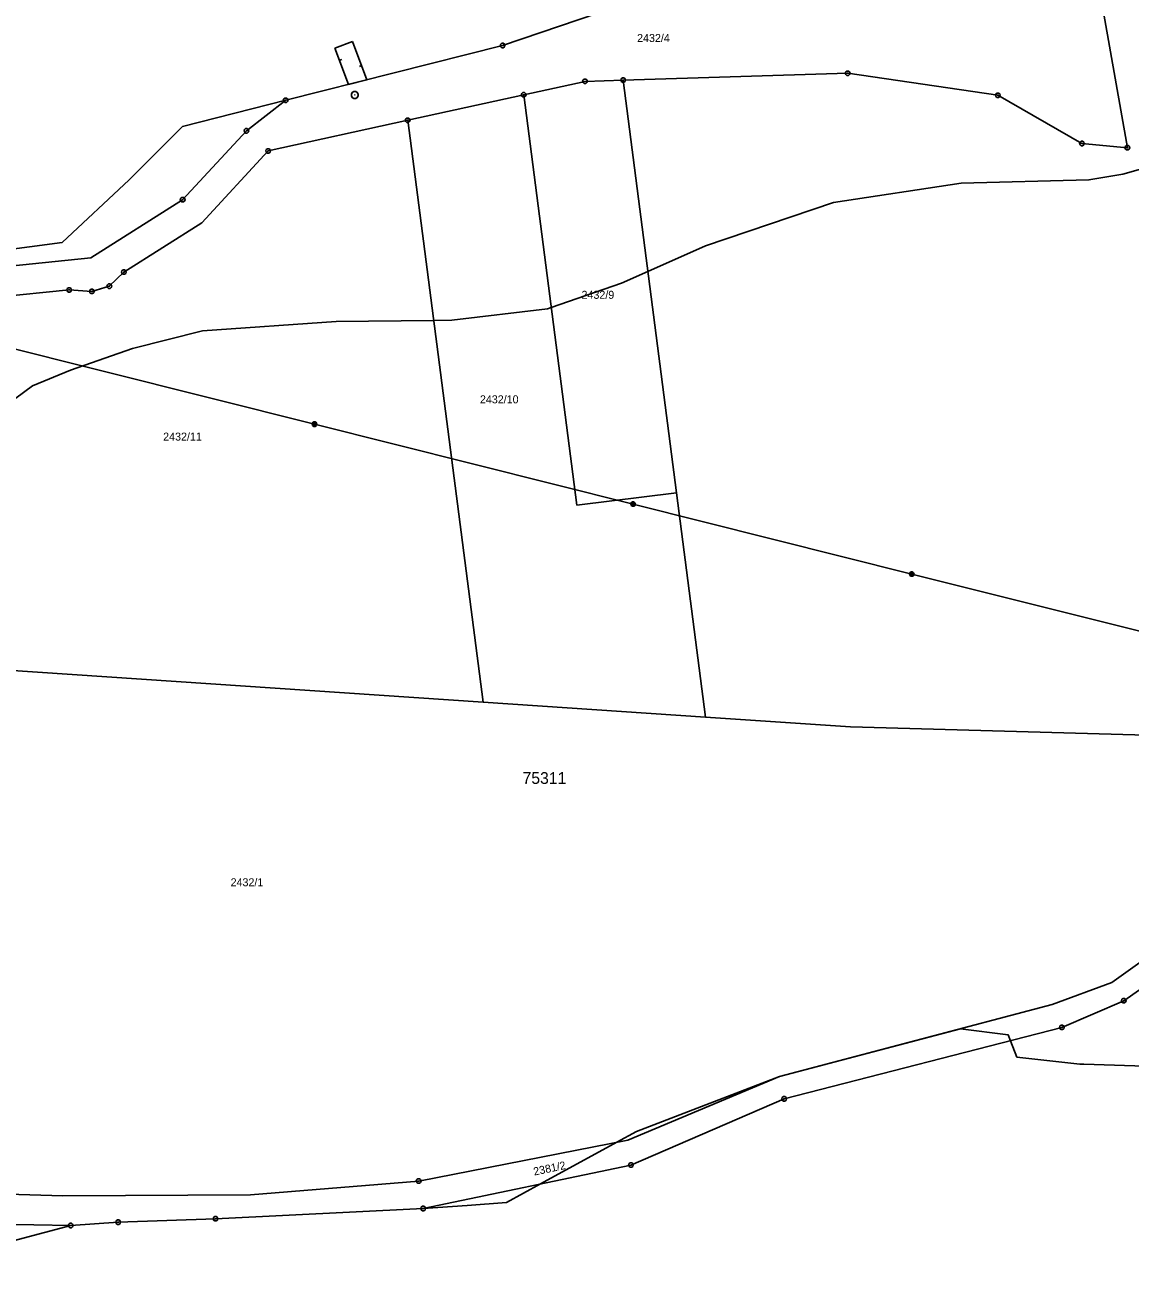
# Model space of a CAD drawing. Extents: x -760611 to -758411, y -1176479 to -1174807.
# Drawn here: x -758977.4 to -758742.6, y -1175366.9 to -1175101.5 of the extents above; entities that cross this region are included whole.
import ezdxf

# ---------------------------------------------------------------- set-up
doc = ezdxf.new("R2010")
doc.units = 0
for name, color, linetype in [('1', 7, 'Continuous'), ('11', 7, 'Continuous'), ('13', 7, 'Continuous'), ('2', 7, 'Continuous'), ('6', 7, 'Continuous'), ('8', 7, 'Continuous')]:
    doc.layers.add(name, color=color, linetype=linetype)

msp = doc.modelspace()

# ---------------------------------------------------------------- linework, layer by layer
at = {"layer": '1'}
for p, q in [((-758855.66, -1175098.98), (-758875.91, -1175105.89)), ((-758748.15, -1175099.24), (-758743.15, -1175127.6)), ((-758875.91, -1175105.89), (-758922, -1175117.53)), ((-758858.39, -1175113.5), (-758871.42, -1175116.36)), ((-758850.29, -1175113.25), (-758858.39, -1175113.5)), ((-758802.58, -1175111.79), (-758850.29, -1175113.25)), ((-758838.93, -1175200.97), (-758850.29, -1175113.25)), ((-758770.67, -1175116.46), (-758802.58, -1175111.79)), ((-758943.96, -1175123.07), (-758922, -1175117.53)), ((-758930.35, -1175124.02), (-758922, -1175117.53)), ((-758871.42, -1175116.36), (-758896.08, -1175121.78)), ((-758871.42, -1175116.36), (-758860.12, -1175203.57)), ((-758752.8, -1175126.72), (-758770.67, -1175116.46)), ((-758943.96, -1175123.07), (-758955.25, -1175134.45)), ((-758943.9, -1175138.65), (-758930.35, -1175124.02)), ((-758896.08, -1175121.78), (-758925.73, -1175128.3)), ((-758896.08, -1175121.78), (-758880.06, -1175245.42)), ((-758743.15, -1175127.6), (-758752.8, -1175126.72)), ((-758925.73, -1175128.3), (-758939.85, -1175143.55)), ((-758955.25, -1175134.45), (-758969.53, -1175147.78)), ((-758963.42, -1175151.02), (-758943.9, -1175138.65)), ((-758939.85, -1175143.55), (-758956.4, -1175154.03)), ((-758969.53, -1175147.78), (-758992.89, -1175150.76)), ((-758994.13, -1175154.13), (-758963.42, -1175151.02)), ((-758956.4, -1175154.03), (-758959.48, -1175157.03)), ((-758968.01, -1175157.83), (-758992.28, -1175160.27)), ((-758963.18, -1175158.15), (-758968.01, -1175157.83)), ((-758959.48, -1175157.03), (-758963.18, -1175158.15)), ((-758860.12, -1175203.57), (-758838.93, -1175200.97)), ((-758832.76, -1175248.61), (-758838.93, -1175200.97)), ((-758880.06, -1175245.42), (-758982.14, -1175238.54)), ((-758880.06, -1175245.42), (-758832.76, -1175248.61)), ((-758832.76, -1175248.61), (-758801.99, -1175250.69)), ((-758695.3, -1175253.59), (-758801.99, -1175250.69)), ((-758730.9, -1175293.88), (-758746.46, -1175305.02)), ((-758743.91, -1175308.85), (-758726.91, -1175296.89)), ((-758746.46, -1175305.02), (-758759.1, -1175309.68)), ((-758759.1, -1175309.68), (-758817.04, -1175324.96)), ((-758743.91, -1175308.85), (-758757.06, -1175314.54)), ((-758757.06, -1175314.54), (-758816.07, -1175329.71)), ((-758817.04, -1175324.96), (-758849.31, -1175338.47)), ((-758816.07, -1175329.71), (-758848.63, -1175343.77)), ((-758849.31, -1175338.47), (-758893.74, -1175347.18)), ((-758848.63, -1175343.77), (-758892.8, -1175353.02)), ((-758893.74, -1175347.18), (-758929.46, -1175350.12)), ((-758969.35, -1175350.34), (-758984.06, -1175349.84)), ((-758929.46, -1175350.12), (-758969.35, -1175350.34)), ((-758936.92, -1175355.2), (-758892.8, -1175353.02)), ((-758991.35, -1175356.15), (-758967.69, -1175356.63)), ((-758967.69, -1175356.63), (-758957.61, -1175355.92)), ((-758957.61, -1175355.92), (-758936.92, -1175355.2))]:
    msp.add_line(p, q, dxfattribs=at)
at = {"layer": '11'}
for points in [[(-758613.2, -1175122.93), (-758673.25, -1175117.07), (-758689.79, -1175118.68), (-758704.22, -1175121.99), (-758744.12, -1175133.22), (-758751.33, -1175134.45), (-758778.47, -1175135.16), (-758805.62, -1175139.26), (-758832.79, -1175148.43), (-758845.03, -1175153.89), (-758850.63, -1175156.38), (-758865.57, -1175161.54), (-758866.34, -1175161.81), (-758886.7, -1175164.24), (-758890.57, -1175164.29), (-758911.29, -1175164.54), (-758939.71, -1175166.52), (-758954.56, -1175170.25), (-758967.72, -1175174.84), (-758975.79, -1175178.19), (-758988.73, -1175187.68)], [(-758658.74, -1175325.4), (-758661.28, -1175325.32), (-758752.38, -1175322.35), (-758753.28, -1175322.32), (-758766.61, -1175320.84), (-758767.99, -1175317.35), (-758768.47, -1175316.14), (-758778.64, -1175314.83), (-758817.04, -1175324.96), (-758847.47, -1175336.66), (-758851.6, -1175338.92), (-758867.88, -1175347.8), (-758875.08, -1175351.73), (-758883.45, -1175352.34), (-758892.8, -1175353.02)], [(-758993.67, -1175366.93), (-758989.69, -1175362.44), (-758985.6, -1175361.36), (-758967.69, -1175356.63), (-758957.61, -1175355.92), (-758936.92, -1175355.2), (-758892.8, -1175353.02)]]:
    msp.add_lwpolyline(points, dxfattribs=at)
at = {"layer": '13'}
for p, q in [((-758911.53, -1175106.42), (-758907.79, -1175105.02)), ((-758907.79, -1175105.02), (-758904.74, -1175113.17)), ((-758908.65, -1175114.16), (-758911.53, -1175106.42)), ((-758910.57, -1175109.01), (-758910.1, -1175108.83)), ((-758905.86, -1175110.17), (-758906.33, -1175110.35)), ((-758904.74, -1175113.17), (-758908.65, -1175114.16))]:
    msp.add_line(p, q, dxfattribs=at)
at = {"layer": '6'}
for p, q in [((-758915.88, -1175186.35), (-758992.56, -1175167.12)), ((-758848.19, -1175203.34), (-758915.88, -1175186.35)), ((-758788.97, -1175218.21), (-758848.19, -1175203.34)), ((-758725.44, -1175234.14), (-758788.97, -1175218.21))]:
    msp.add_line(p, q, dxfattribs=at)
for points in [[(-758916.03, -1175185.87), (-758915.72, -1175185.87), (-758915.47, -1175186.05), (-758915.37, -1175186.34), (-758915.47, -1175186.63), (-758915.72, -1175186.81), (-758916.03, -1175186.81), (-758916.28, -1175186.63), (-758916.38, -1175186.34), (-758916.28, -1175186.05), (-758916.03, -1175185.87), (-758916, -1175185.91), (-758915.76, -1175185.91), (-758915.6, -1175185.99), (-758916.16, -1175185.99), (-758916.24, -1175186.07), (-758915.52, -1175186.07), (-758915.52, -1175186.15), (-758916.24, -1175186.15), (-758916.28, -1175186.23), (-758915.48, -1175186.23), (-758915.44, -1175186.31), (-758916.32, -1175186.31), (-758916.32, -1175186.39), (-758915.44, -1175186.39), (-758915.47, -1175186.47), (-758916.28, -1175186.47), (-758916.27, -1175186.55), (-758915.46, -1175186.55), (-758915.51, -1175186.63), (-758916.23, -1175186.63), (-758916.15, -1175186.71), (-758915.59, -1175186.71), (-758915.7, -1175186.79), (-758916.04, -1175186.79)], [(-758848.34, -1175202.86), (-758848.03, -1175202.86), (-758847.78, -1175203.04), (-758847.68, -1175203.33), (-758847.78, -1175203.62), (-758848.03, -1175203.8), (-758848.34, -1175203.8), (-758848.59, -1175203.62), (-758848.69, -1175203.33), (-758848.59, -1175203.04), (-758848.34, -1175202.86), (-758848.31, -1175202.9), (-758848.07, -1175202.9), (-758847.91, -1175202.98), (-758848.47, -1175202.98), (-758848.55, -1175203.06), (-758847.83, -1175203.06), (-758847.83, -1175203.14), (-758848.55, -1175203.14), (-758848.59, -1175203.22), (-758847.79, -1175203.22), (-758847.75, -1175203.3), (-758848.63, -1175203.3), (-758848.63, -1175203.38), (-758847.75, -1175203.38), (-758847.78, -1175203.46), (-758848.59, -1175203.46), (-758848.58, -1175203.54), (-758847.77, -1175203.54), (-758847.82, -1175203.62), (-758848.54, -1175203.62), (-758848.46, -1175203.7), (-758847.9, -1175203.7), (-758848.01, -1175203.78), (-758848.35, -1175203.78)], [(-758789.12, -1175217.73), (-758788.81, -1175217.73), (-758788.56, -1175217.91), (-758788.46, -1175218.2), (-758788.56, -1175218.49), (-758788.81, -1175218.67), (-758789.12, -1175218.67), (-758789.37, -1175218.49), (-758789.47, -1175218.2), (-758789.37, -1175217.91), (-758789.12, -1175217.73), (-758789.09, -1175217.77), (-758788.85, -1175217.77), (-758788.69, -1175217.85), (-758789.25, -1175217.85), (-758789.33, -1175217.93), (-758788.61, -1175217.93), (-758788.61, -1175218.01), (-758789.33, -1175218.01), (-758789.37, -1175218.09), (-758788.57, -1175218.09), (-758788.53, -1175218.17), (-758789.41, -1175218.17), (-758789.41, -1175218.25), (-758788.53, -1175218.25), (-758788.56, -1175218.33), (-758789.37, -1175218.33), (-758789.36, -1175218.41), (-758788.55, -1175218.41), (-758788.6, -1175218.49), (-758789.32, -1175218.49), (-758789.24, -1175218.57), (-758788.68, -1175218.57), (-758788.79, -1175218.65), (-758789.13, -1175218.65)]]:
    msp.add_lwpolyline(points, dxfattribs=at)
at = {"layer": '8'}
for p, q in [((-758876.03, -1175105.89), (-758875.79, -1175105.89)), ((-758858.51, -1175113.5), (-758858.27, -1175113.5)), ((-758850.41, -1175113.25), (-758850.17, -1175113.25)), ((-758802.7, -1175111.79), (-758802.46, -1175111.79)), ((-758922.12, -1175117.53), (-758921.88, -1175117.53)), ((-758907.37, -1175116.4), (-758907.27, -1175116.4)), ((-758871.54, -1175116.36), (-758871.3, -1175116.36)), ((-758770.79, -1175116.46), (-758770.55, -1175116.46)), ((-758930.47, -1175124.02), (-758930.23, -1175124.02)), ((-758896.2, -1175121.78), (-758895.96, -1175121.78)), ((-758752.92, -1175126.72), (-758752.68, -1175126.72)), ((-758925.85, -1175128.3), (-758925.61, -1175128.3)), ((-758743.27, -1175127.6), (-758743.03, -1175127.6)), ((-758944.02, -1175138.65), (-758943.78, -1175138.65)), ((-758956.52, -1175154.03), (-758956.28, -1175154.03)), ((-758968.13, -1175157.83), (-758967.89, -1175157.83)), ((-758963.3, -1175158.15), (-758963.06, -1175158.15)), ((-758959.6, -1175157.03), (-758959.36, -1175157.03)), ((-758744.03, -1175308.85), (-758743.79, -1175308.85)), ((-758757.18, -1175314.54), (-758756.94, -1175314.54)), ((-758816.19, -1175329.71), (-758815.95, -1175329.71)), ((-758848.75, -1175343.77), (-758848.51, -1175343.77)), ((-758893.86, -1175347.18), (-758893.62, -1175347.18)), ((-758892.92, -1175353.02), (-758892.68, -1175353.02)), ((-758967.81, -1175356.63), (-758967.57, -1175356.63)), ((-758957.73, -1175355.92), (-758957.49, -1175355.92)), ((-758937.04, -1175355.2), (-758936.8, -1175355.2))]:
    msp.add_line(p, q, dxfattribs=at)
for points in [[(-758875.76, -1175105.41), (-758875.51, -1175105.59), (-758875.41, -1175105.88), (-758875.51, -1175106.17), (-758875.76, -1175106.35), (-758876.07, -1175106.35), (-758876.32, -1175106.17), (-758876.42, -1175105.88), (-758876.32, -1175105.59), (-758876.07, -1175105.41)], [(-758858.24, -1175113.02), (-758857.99, -1175113.2), (-758857.89, -1175113.49), (-758857.99, -1175113.78), (-758858.24, -1175113.96), (-758858.55, -1175113.96), (-758858.8, -1175113.78), (-758858.9, -1175113.49), (-758858.8, -1175113.2), (-758858.55, -1175113.02)], [(-758850.14, -1175112.77), (-758849.89, -1175112.95), (-758849.79, -1175113.24), (-758849.89, -1175113.53), (-758850.14, -1175113.71), (-758850.45, -1175113.71), (-758850.7, -1175113.53), (-758850.8, -1175113.24), (-758850.7, -1175112.95), (-758850.45, -1175112.77)], [(-758802.43, -1175111.31), (-758802.18, -1175111.49), (-758802.08, -1175111.78), (-758802.18, -1175112.07), (-758802.43, -1175112.25), (-758802.74, -1175112.25), (-758802.99, -1175112.07), (-758803.09, -1175111.78), (-758802.99, -1175111.49), (-758802.74, -1175111.31)], [(-758907.13, -1175115.68), (-758906.79, -1175115.87), (-758906.6, -1175116.21), (-758906.6, -1175116.6), (-758906.79, -1175116.94), (-758907.13, -1175117.13), (-758907.52, -1175117.13), (-758907.86, -1175116.94), (-758908.05, -1175116.6), (-758908.05, -1175116.21), (-758907.86, -1175115.87), (-758907.52, -1175115.68)], [(-758871.27, -1175115.88), (-758871.02, -1175116.06), (-758870.92, -1175116.35), (-758871.02, -1175116.64), (-758871.27, -1175116.82), (-758871.58, -1175116.82), (-758871.83, -1175116.64), (-758871.93, -1175116.35), (-758871.83, -1175116.06), (-758871.58, -1175115.88)], [(-758770.52, -1175115.98), (-758770.27, -1175116.16), (-758770.17, -1175116.45), (-758770.27, -1175116.74), (-758770.52, -1175116.92), (-758770.83, -1175116.92), (-758771.08, -1175116.74), (-758771.18, -1175116.45), (-758771.08, -1175116.16), (-758770.83, -1175115.98)], [(-758921.85, -1175117.05), (-758921.6, -1175117.23), (-758921.5, -1175117.52), (-758921.6, -1175117.81), (-758921.85, -1175117.99), (-758922.16, -1175117.99), (-758922.41, -1175117.81), (-758922.51, -1175117.52), (-758922.41, -1175117.23), (-758922.16, -1175117.05)], [(-758895.93, -1175121.3), (-758895.68, -1175121.48), (-758895.58, -1175121.77), (-758895.68, -1175122.06), (-758895.93, -1175122.24), (-758896.24, -1175122.24), (-758896.49, -1175122.06), (-758896.59, -1175121.77), (-758896.49, -1175121.48), (-758896.24, -1175121.3)], [(-758930.2, -1175123.54), (-758929.95, -1175123.72), (-758929.85, -1175124.01), (-758929.95, -1175124.3), (-758930.2, -1175124.48), (-758930.51, -1175124.48), (-758930.76, -1175124.3), (-758930.86, -1175124.01), (-758930.76, -1175123.72), (-758930.51, -1175123.54)], [(-758752.65, -1175126.24), (-758752.4, -1175126.42), (-758752.3, -1175126.71), (-758752.4, -1175127), (-758752.65, -1175127.18), (-758752.96, -1175127.18), (-758753.21, -1175127), (-758753.31, -1175126.71), (-758753.21, -1175126.42), (-758752.96, -1175126.24)], [(-758925.58, -1175127.82), (-758925.33, -1175128), (-758925.23, -1175128.29), (-758925.33, -1175128.58), (-758925.58, -1175128.76), (-758925.89, -1175128.76), (-758926.14, -1175128.58), (-758926.24, -1175128.29), (-758926.14, -1175128), (-758925.89, -1175127.82)], [(-758743, -1175127.12), (-758742.75, -1175127.3), (-758742.65, -1175127.59), (-758742.75, -1175127.88), (-758743, -1175128.06), (-758743.31, -1175128.06), (-758743.56, -1175127.88), (-758743.66, -1175127.59), (-758743.56, -1175127.3), (-758743.31, -1175127.12)], [(-758943.75, -1175138.17), (-758943.5, -1175138.35), (-758943.4, -1175138.64), (-758943.5, -1175138.93), (-758943.75, -1175139.11), (-758944.06, -1175139.11), (-758944.31, -1175138.93), (-758944.41, -1175138.64), (-758944.31, -1175138.35), (-758944.06, -1175138.17)], [(-758956.25, -1175153.55), (-758956, -1175153.73), (-758955.9, -1175154.02), (-758956, -1175154.31), (-758956.25, -1175154.49), (-758956.56, -1175154.49), (-758956.81, -1175154.31), (-758956.91, -1175154.02), (-758956.81, -1175153.73), (-758956.56, -1175153.55)], [(-758967.86, -1175157.35), (-758967.61, -1175157.53), (-758967.51, -1175157.82), (-758967.61, -1175158.11), (-758967.86, -1175158.29), (-758968.17, -1175158.29), (-758968.42, -1175158.11), (-758968.52, -1175157.82), (-758968.42, -1175157.53), (-758968.17, -1175157.35)], [(-758963.03, -1175157.67), (-758962.78, -1175157.85), (-758962.68, -1175158.14), (-758962.78, -1175158.43), (-758963.03, -1175158.61), (-758963.34, -1175158.61), (-758963.59, -1175158.43), (-758963.69, -1175158.14), (-758963.59, -1175157.85), (-758963.34, -1175157.67)], [(-758959.33, -1175156.55), (-758959.08, -1175156.73), (-758958.98, -1175157.02), (-758959.08, -1175157.31), (-758959.33, -1175157.49), (-758959.64, -1175157.49), (-758959.89, -1175157.31), (-758959.99, -1175157.02), (-758959.89, -1175156.73), (-758959.64, -1175156.55)], [(-758743.76, -1175308.37), (-758743.51, -1175308.55), (-758743.41, -1175308.84), (-758743.51, -1175309.13), (-758743.76, -1175309.31), (-758744.07, -1175309.31), (-758744.32, -1175309.13), (-758744.42, -1175308.84), (-758744.32, -1175308.55), (-758744.07, -1175308.37)], [(-758756.91, -1175314.06), (-758756.66, -1175314.24), (-758756.56, -1175314.53), (-758756.66, -1175314.82), (-758756.91, -1175315), (-758757.22, -1175315), (-758757.47, -1175314.82), (-758757.57, -1175314.53), (-758757.47, -1175314.24), (-758757.22, -1175314.06)], [(-758815.92, -1175329.23), (-758815.67, -1175329.41), (-758815.57, -1175329.7), (-758815.67, -1175329.99), (-758815.92, -1175330.17), (-758816.23, -1175330.17), (-758816.48, -1175329.99), (-758816.58, -1175329.7), (-758816.48, -1175329.41), (-758816.23, -1175329.23)], [(-758848.48, -1175343.29), (-758848.23, -1175343.47), (-758848.13, -1175343.76), (-758848.23, -1175344.05), (-758848.48, -1175344.23), (-758848.79, -1175344.23), (-758849.04, -1175344.05), (-758849.14, -1175343.76), (-758849.04, -1175343.47), (-758848.79, -1175343.29)], [(-758893.59, -1175346.7), (-758893.34, -1175346.88), (-758893.24, -1175347.17), (-758893.34, -1175347.46), (-758893.59, -1175347.64), (-758893.9, -1175347.64), (-758894.15, -1175347.46), (-758894.25, -1175347.17), (-758894.15, -1175346.88), (-758893.9, -1175346.7)], [(-758936.77, -1175354.72), (-758936.52, -1175354.9), (-758936.42, -1175355.19), (-758936.52, -1175355.48), (-758936.77, -1175355.66), (-758937.08, -1175355.66), (-758937.33, -1175355.48), (-758937.43, -1175355.19), (-758937.33, -1175354.9), (-758937.08, -1175354.72)], [(-758892.65, -1175352.54), (-758892.4, -1175352.72), (-758892.3, -1175353.01), (-758892.4, -1175353.3), (-758892.65, -1175353.48), (-758892.96, -1175353.48), (-758893.21, -1175353.3), (-758893.31, -1175353.01), (-758893.21, -1175352.72), (-758892.96, -1175352.54)], [(-758967.54, -1175356.15), (-758967.29, -1175356.33), (-758967.19, -1175356.62), (-758967.29, -1175356.91), (-758967.54, -1175357.09), (-758967.85, -1175357.09), (-758968.1, -1175356.91), (-758968.2, -1175356.62), (-758968.1, -1175356.33), (-758967.85, -1175356.15)], [(-758957.46, -1175355.44), (-758957.21, -1175355.62), (-758957.11, -1175355.91), (-758957.21, -1175356.2), (-758957.46, -1175356.38), (-758957.77, -1175356.38), (-758958.02, -1175356.2), (-758958.12, -1175355.91), (-758958.02, -1175355.62), (-758957.77, -1175355.44)]]:
    msp.add_lwpolyline(points, close=True, dxfattribs=at)

# ---------------------------------------------------------------- texts
at = {"layer": '11'}
msp.add_text('75311', height=2.5, dxfattribs=at).set_placement((-758871.67, -1175262.79))
at = {"layer": '2'}
for s, p in [('2432/4', (-758847.33, -1175105.14)), ('2432/9', (-758859.14, -1175159.71)), ('2432/10', (-758880.73, -1175181.92)), ('2432/11', (-758948.04, -1175189.84)), ('2432/1', (-758933.71, -1175284.54))]:
    msp.add_text(s, height=1.7, dxfattribs=at).set_placement(p)
msp.add_text('2381/2', height=1.7, rotation=11.8602, dxfattribs=at).set_placement((-758869.18, -1175346.02))

doc.saveas('drawing.dxf')
